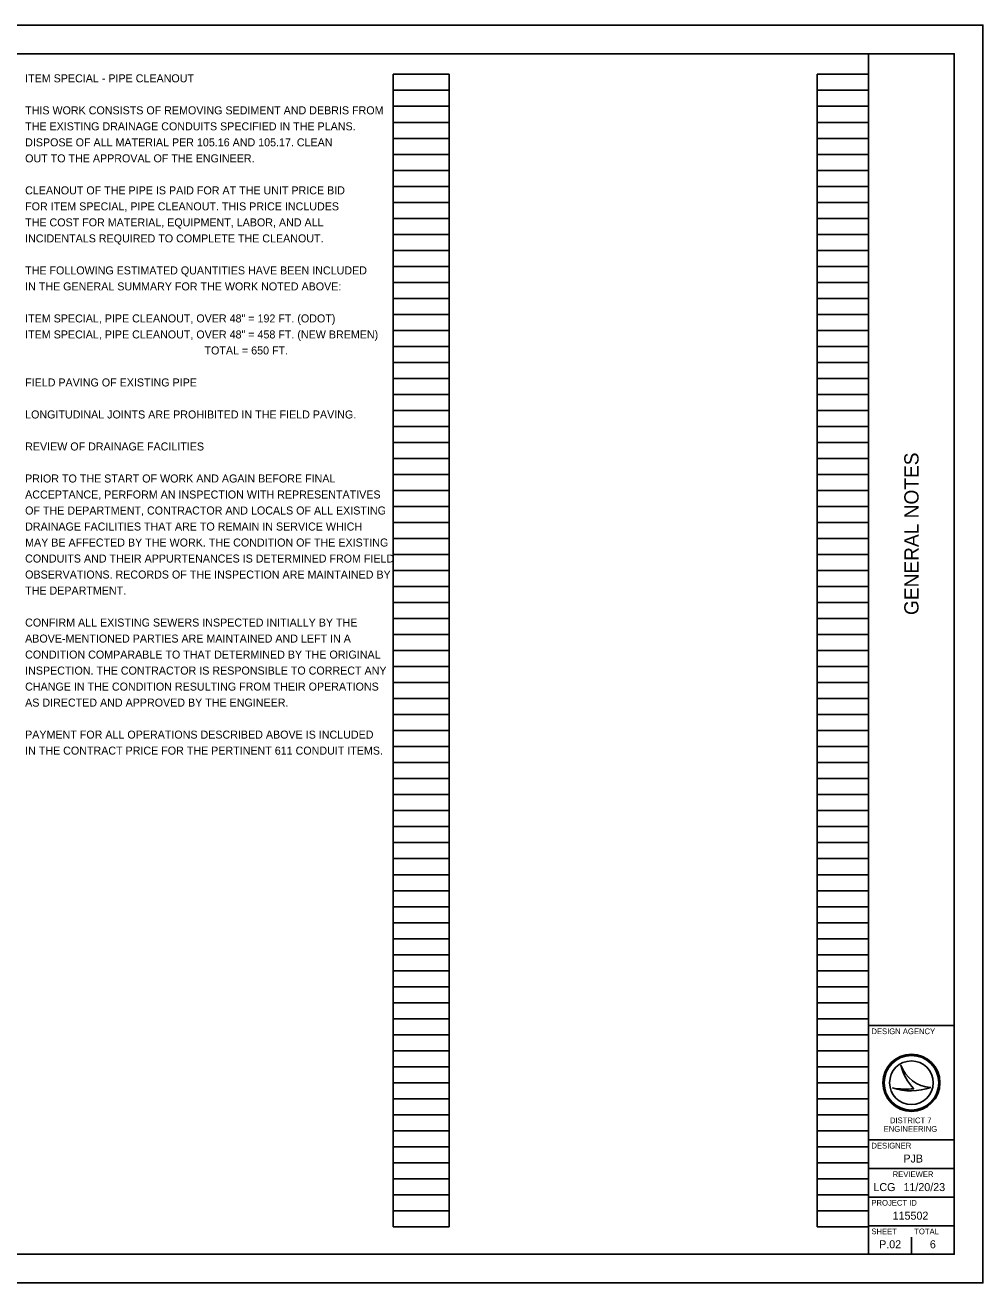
# Model space of a CAD drawing. Extents: x 0 to 34, y 0 to 22.
# Drawn here: x 17.24 to 34, y 0 to 22 of the extents above; entities that cross this region are included whole.
import ezdxf

# ---------------------------------------------------------------- set-up
doc = ezdxf.new("R2010")
doc.units = 0
for name, color, linetype in [('SC_Scratch1', 7, 'Continuous'), ('SH_Border', 7, 'Continuous'), ('SH_Cut_Line', 7, 'Continuous'), ('SH_Data', 7, 'Continuous'), ('SH_Text', 7, 'Continuous')]:
    doc.layers.add(name, color=color, linetype=linetype)

msp = doc.modelspace()

# ---------------------------------------------------------------- linework, layer by layer
at = {"layer": 'SC_Scratch1'}
for p, q in [((23.68, 0.98), (23.68, 21.14)), ((23.68, 21.14), (24.66, 21.14)), ((24.66, 0.98), (24.66, 21.14)), ((31.1, 0.98), (31.1, 21.14)), ((31.1, 21.14), (32, 21.14)), ((32, 0.98), (32, 21.14)), ((23.68, 20.86), (24.66, 20.86)), ((31.1, 20.86), (32, 20.86)), ((23.68, 20.58), (24.66, 20.58)), ((31.1, 20.58), (32, 20.58)), ((23.68, 20.3), (24.66, 20.3)), ((31.1, 20.3), (32, 20.3)), ((23.68, 20.02), (24.66, 20.02)), ((31.1, 20.02), (32, 20.02)), ((23.68, 19.74), (24.66, 19.74)), ((31.1, 19.74), (32, 19.74)), ((23.68, 19.46), (24.66, 19.46)), ((31.1, 19.46), (32, 19.46)), ((23.68, 19.18), (24.66, 19.18)), ((31.1, 19.18), (32, 19.18)), ((23.68, 18.9), (24.66, 18.9)), ((31.1, 18.9), (32, 18.9)), ((23.68, 18.62), (24.66, 18.62)), ((31.1, 18.62), (32, 18.62)), ((23.68, 18.34), (24.66, 18.34)), ((31.1, 18.34), (32, 18.34)), ((23.68, 18.06), (24.66, 18.06)), ((31.1, 18.06), (32, 18.06)), ((23.68, 17.78), (24.66, 17.78)), ((31.1, 17.78), (32, 17.78)), ((23.68, 17.5), (24.66, 17.5)), ((31.1, 17.5), (32, 17.5)), ((23.68, 17.22), (24.66, 17.22)), ((31.1, 17.22), (32, 17.22)), ((23.68, 16.94), (24.66, 16.94)), ((31.1, 16.94), (32, 16.94)), ((23.68, 16.66), (24.66, 16.66)), ((31.1, 16.66), (32, 16.66)), ((23.68, 16.38), (24.66, 16.38)), ((31.1, 16.38), (32, 16.38)), ((23.68, 16.1), (24.66, 16.1)), ((31.1, 16.1), (32, 16.1)), ((23.68, 15.82), (24.66, 15.82)), ((31.1, 15.82), (32, 15.82)), ((23.68, 15.54), (24.66, 15.54)), ((31.1, 15.54), (32, 15.54)), ((23.68, 15.26), (24.66, 15.26)), ((31.1, 15.26), (32, 15.26)), ((23.68, 14.98), (24.66, 14.98)), ((31.1, 14.98), (32, 14.98)), ((23.68, 14.7), (24.66, 14.7)), ((31.1, 14.7), (32, 14.7)), ((23.68, 14.42), (24.66, 14.42)), ((31.1, 14.42), (32, 14.42)), ((23.68, 14.14), (24.66, 14.14)), ((31.1, 14.14), (32, 14.14)), ((23.68, 13.86), (24.66, 13.86)), ((31.1, 13.86), (32, 13.86)), ((23.68, 13.58), (24.66, 13.58)), ((31.1, 13.58), (32, 13.58)), ((23.68, 13.3), (24.66, 13.3)), ((31.1, 13.3), (32, 13.3)), ((23.68, 13.02), (24.66, 13.02)), ((31.1, 13.02), (32, 13.02)), ((23.68, 12.74), (24.66, 12.74)), ((31.1, 12.74), (32, 12.74)), ((23.68, 12.46), (24.66, 12.46)), ((31.1, 12.46), (32, 12.46)), ((23.68, 12.18), (24.66, 12.18)), ((31.1, 12.18), (32, 12.18)), ((23.68, 11.9), (24.66, 11.9)), ((31.1, 11.9), (32, 11.9)), ((23.68, 11.62), (24.66, 11.62)), ((31.1, 11.62), (32, 11.62)), ((23.68, 11.34), (24.66, 11.34)), ((31.1, 11.34), (32, 11.34)), ((23.68, 11.06), (24.66, 11.06)), ((31.1, 11.06), (32, 11.06)), ((23.68, 10.78), (24.66, 10.78)), ((31.1, 10.78), (32, 10.78)), ((23.68, 10.5), (24.66, 10.5)), ((31.1, 10.5), (32, 10.5)), ((23.68, 10.22), (24.66, 10.22)), ((31.1, 10.22), (32, 10.22)), ((23.68, 9.94), (24.66, 9.94)), ((31.1, 9.94), (32, 9.94)), ((23.68, 9.66), (24.66, 9.66)), ((31.1, 9.66), (32, 9.66)), ((23.68, 9.38), (24.66, 9.38)), ((31.1, 9.38), (32, 9.38)), ((23.68, 9.1), (24.66, 9.1)), ((31.1, 9.1), (32, 9.1)), ((23.68, 8.82), (24.66, 8.82)), ((31.1, 8.82), (32, 8.82)), ((23.68, 8.54), (24.66, 8.54)), ((31.1, 8.54), (32, 8.54)), ((23.68, 8.26), (24.66, 8.26)), ((31.1, 8.26), (32, 8.26)), ((23.68, 7.98), (24.66, 7.98)), ((31.1, 7.98), (32, 7.98)), ((23.68, 7.7), (24.66, 7.7)), ((31.1, 7.7), (32, 7.7)), ((23.68, 7.42), (24.66, 7.42)), ((31.1, 7.42), (32, 7.42)), ((23.68, 7.14), (24.66, 7.14)), ((31.1, 7.14), (32, 7.14)), ((23.68, 6.86), (24.66, 6.86)), ((31.1, 6.86), (32, 6.86)), ((23.68, 6.58), (24.66, 6.58)), ((31.1, 6.58), (32, 6.58)), ((23.68, 6.3), (24.66, 6.3)), ((31.1, 6.3), (32, 6.3)), ((23.68, 6.02), (24.66, 6.02)), ((31.1, 6.02), (32, 6.02)), ((23.68, 5.74), (24.66, 5.74)), ((31.1, 5.74), (32, 5.74)), ((23.68, 5.46), (24.66, 5.46)), ((31.1, 5.46), (32, 5.46)), ((23.68, 5.18), (24.66, 5.18)), ((31.1, 5.18), (32, 5.18)), ((23.68, 4.9), (24.66, 4.9)), ((31.1, 4.9), (32, 4.9)), ((23.68, 4.62), (24.66, 4.62)), ((31.1, 4.62), (32, 4.62)), ((23.68, 4.34), (24.66, 4.34)), ((31.1, 4.34), (32, 4.34)), ((23.68, 4.06), (24.66, 4.06)), ((31.1, 4.06), (32, 4.06)), ((23.68, 3.78), (24.66, 3.78)), ((31.1, 3.78), (32, 3.78)), ((23.68, 3.5), (24.66, 3.5)), ((31.1, 3.5), (32, 3.5)), ((23.68, 3.22), (24.66, 3.22)), ((31.1, 3.22), (32, 3.22)), ((23.68, 2.94), (24.66, 2.94)), ((31.1, 2.94), (32, 2.94)), ((23.68, 2.66), (24.66, 2.66)), ((31.1, 2.66), (32, 2.66)), ((23.68, 2.38), (24.66, 2.38)), ((31.1, 2.38), (32, 2.38)), ((23.68, 2.1), (24.66, 2.1)), ((31.1, 2.1), (32, 2.1)), ((23.68, 1.82), (24.66, 1.82)), ((31.1, 1.82), (32, 1.82)), ((23.68, 1.54), (24.66, 1.54)), ((31.1, 1.54), (32, 1.54)), ((23.68, 1.26), (24.66, 1.26)), ((31.1, 1.26), (32, 1.26)), ((23.68, 0.98), (24.66, 0.98)), ((31.1, 0.98), (32, 0.98))]:
    msp.add_line(p, q, dxfattribs=at)
at = {"layer": 'SH_Border'}
for p, q in [((32, 0.5), (32, 21.5)), ((32, 4.5), (33.5, 4.5)), ((32, 2.5), (33.5, 2.5)), ((32, 2), (33.5, 2)), ((32, 1.5), (33.5, 1.5)), ((32, 1), (33.5, 1))]:
    msp.add_line(p, q, dxfattribs=at)
msp.add_lwpolyline([(1.5, 21.5), (33.5, 21.5), (33.5, 0.5), (1.5, 0.5)], close=True, dxfattribs=at)
at = {"layer": 'SH_Cut_Line'}
msp.add_lwpolyline([(0, 0), (34, 0), (34, 22), (0, 22)], close=True, dxfattribs=at)
at = {"layer": 'SH_Data'}
for p, q in [((32.567, 3.81), (32.567, 3.81)), ((32.417, 3.41), (32.417, 3.41)), ((32.75, 3.5), (32.75, 3.5)), ((33.087, 3.419), (33.087, 3.419)), ((32.375, 0.675), (32.375, 0.675)), ((32.75, 0.5), (32.75, 0.8))]:
    msp.add_line(p, q, dxfattribs=at)
for radius in [0.5, 0.477, 0.477, 0.382]:
    msp.add_circle((32.75, 3.5), radius, dxfattribs=at)
for centre, radius, start, end in [((33.116, 3.998), 0.58, 198.9257, 198.9319), ((33.347, 3.97), 0.796, 191.6379, 191.6421), ((33.116, 3.998), 0.58, 198.9319, 267.1657), ((33.347, 3.97), 0.796, 191.6421, 226.0947), ((32.739, 4.37), 1.013, 251.4576, 290.0832), ((32.648, 4.654), 1.266, 259.4964, 259.4995), ((32.739, 4.37), 1.013, 251.4527, 251.4576), ((32.648, 4.654), 1.266, 259.4995, 276.6672)]:
    msp.add_arc(centre, radius, start, end, dxfattribs=at)

# ---------------------------------------------------------------- texts
msp.add_text('GENERAL NOTES', height=0.25, rotation=90, dxfattribs=at).set_placement((32.875, 11.682))
for s, height, p in [('DESIGN AGENCY', 0.1, (32.05, 4.35)), ('DESIGNER', 0.1, (32.05, 2.35)), ('PJB', 0.14, (32.61, 2.105)), ('REVIEWER', 0.1, (32.422, 1.85)), ('LCG', 0.14, (32.085, 1.605)), ('11/20/23', 0.14, (32.611, 1.605)), ('PROJECT ID', 0.1, (32.05, 1.35)), ('115502', 0.14, (32.421, 1.105)), ('SHEET', 0.1, (32.05, 0.85)), ('TOTAL', 0.1, (32.8, 0.85)), ('P.02', 0.14, (32.185, 0.605)), ('6', 0.14, (33.073, 0.605))]:
    msp.add_text(s, height=height, dxfattribs=at).set_placement(p)
at = {"layer": 'SH_Text'}
for s, height, p in [('ITEM SPECIAL - PIPE CLEANOUT', 0.14, (17.24, 21)), ('THIS WORK CONSISTS OF REMOVING SEDIMENT AND DEBRIS FROM', 0.14, (17.24, 20.44)), ('THE EXISTING DRAINAGE CONDUITS SPECIFIED IN THE PLANS.', 0.14, (17.24, 20.16)), ('DISPOSE OF ALL MATERIAL PER 105.16 AND 105.17. CLEAN', 0.14, (17.24, 19.88)), ('OUT TO THE APPROVAL OF THE ENGINEER.', 0.14, (17.24, 19.6)), ('CLEANOUT OF THE PIPE IS PAID FOR AT THE UNIT PRICE BID', 0.14, (17.24, 19.04)), ('FOR ITEM SPECIAL, PIPE CLEANOUT. THIS PRICE INCLUDES', 0.14, (17.24, 18.76)), ('THE COST FOR MATERIAL, EQUIPMENT, LABOR, AND ALL', 0.14, (17.24, 18.48)), ('INCIDENTALS REQUIRED TO COMPLETE THE CLEANOUT.', 0.14, (17.24, 18.2)), ('THE FOLLOWING ESTIMATED QUANTITIES HAVE BEEN INCLUDED', 0.14, (17.24, 17.64)), ('IN THE GENERAL SUMMARY FOR THE WORK NOTED ABOVE:', 0.14, (17.24, 17.36)), ('ITEM SPECIAL, PIPE CLEANOUT, OVER 48" = 192 FT. (ODOT) ', 0.14, (17.24, 16.8)), ('ITEM SPECIAL, PIPE CLEANOUT, OVER 48" = 458 FT. (NEW BREMEN)', 0.14, (17.24, 16.52)), ('TOTAL = 650 FT.', 0.14, (20.379, 16.24)), ('FIELD PAVING OF EXISTING PIPE', 0.14, (17.24, 15.68)), ('LONGITUDINAL JOINTS ARE PROHIBITED IN THE FIELD PAVING.', 0.14, (17.24, 15.12)), ('REVIEW OF DRAINAGE FACILITIES', 0.14, (17.24, 14.56)), ('PRIOR TO THE START OF WORK AND AGAIN BEFORE FINAL', 0.14, (17.24, 14)), ('ACCEPTANCE, PERFORM AN INSPECTION WITH REPRESENTATIVES', 0.14, (17.24, 13.72)), ('OF THE DEPARTMENT, CONTRACTOR AND LOCALS OF ALL EXISTING', 0.14, (17.24, 13.44)), ('DRAINAGE FACILITIES THAT ARE TO REMAIN IN SERVICE WHICH', 0.14, (17.24, 13.16)), ('MAY BE AFFECTED BY THE WORK. THE CONDITION OF THE EXISTING', 0.14, (17.24, 12.88)), ('CONDUITS AND THEIR APPURTENANCES IS DETERMINED FROM FIELD', 0.14, (17.24, 12.6)), ('OBSERVATIONS. RECORDS OF THE INSPECTION ARE MAINTAINED BY', 0.14, (17.24, 12.32)), ('THE DEPARTMENT.', 0.14, (17.24, 12.04)), ('CONFIRM ALL EXISTING SEWERS INSPECTED INITIALLY BY THE', 0.14, (17.24, 11.48)), ('ABOVE-MENTIONED PARTIES ARE MAINTAINED AND LEFT IN A', 0.14, (17.24, 11.2)), ('CONDITION COMPARABLE TO THAT DETERMINED BY THE ORIGINAL', 0.14, (17.24, 10.92)), ('INSPECTION. THE CONTRACTOR IS RESPONSIBLE TO CORRECT ANY', 0.14, (17.24, 10.64)), ('CHANGE IN THE CONDITION RESULTING FROM THEIR OPERATIONS', 0.14, (17.24, 10.36)), ('AS DIRECTED AND APPROVED BY THE ENGINEER.', 0.14, (17.24, 10.08)), ('PAYMENT FOR ALL OPERATIONS DESCRIBED ABOVE IS INCLUDED', 0.14, (17.24, 9.52)), ('IN THE CONTRACT PRICE FOR THE PERTINENT 611 CONDUIT ITEMS.', 0.14, (17.24, 9.24)), ('DISTRICT 7', 0.1, (32.374, 2.792)), ('ENGINEERING', 0.1, (32.265, 2.642))]:
    msp.add_text(s, height=height, dxfattribs=at).set_placement(p)

doc.saveas('drawing.dxf')
